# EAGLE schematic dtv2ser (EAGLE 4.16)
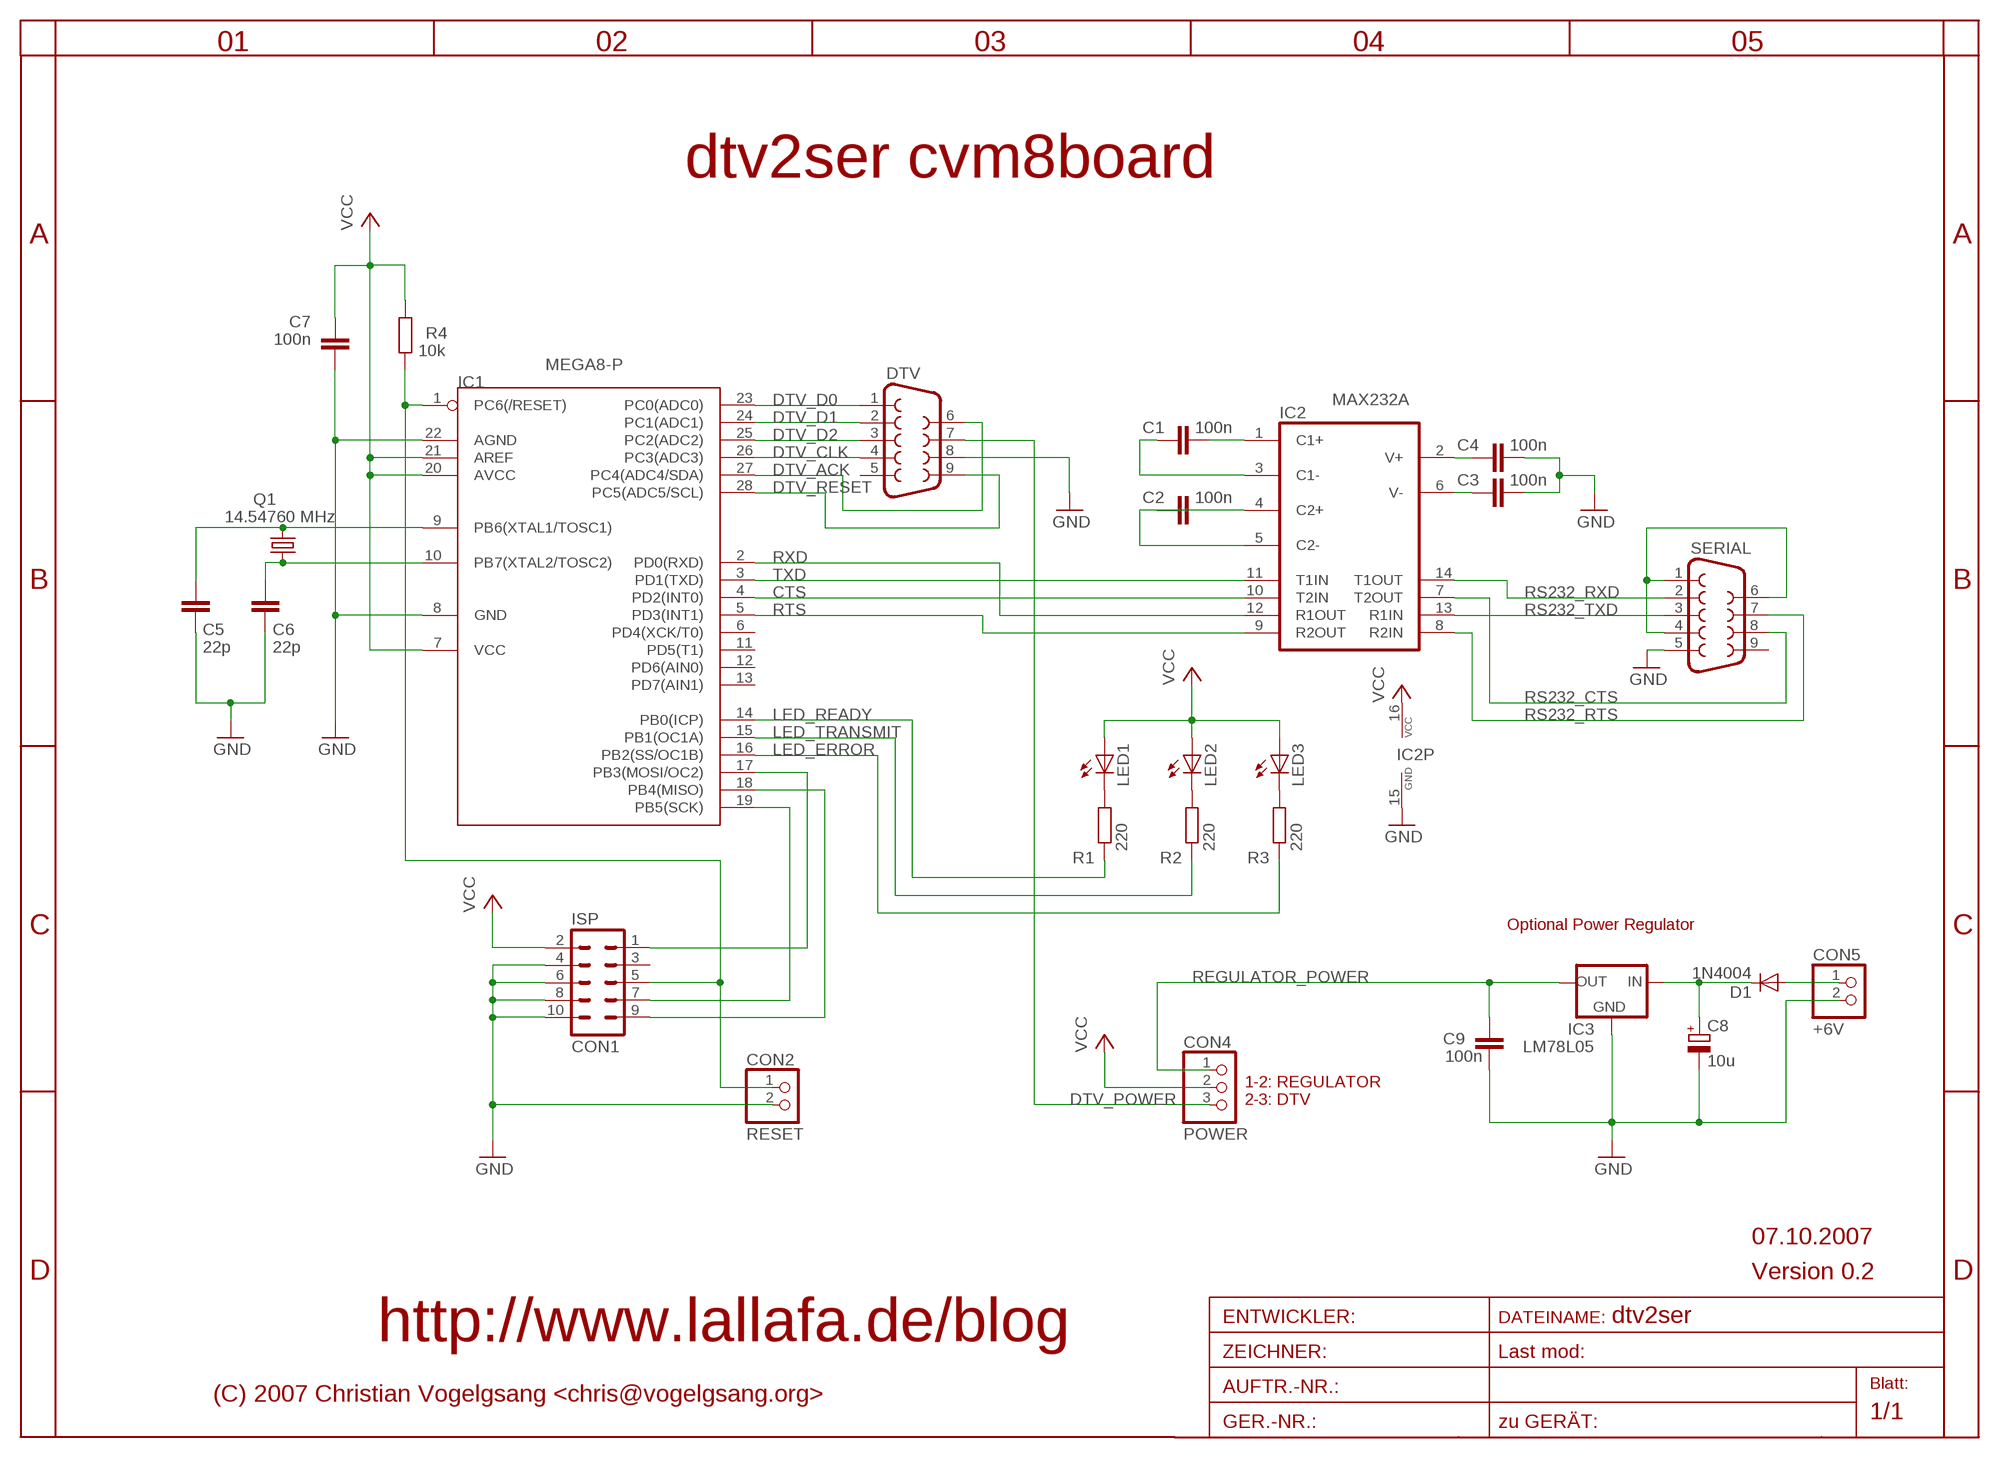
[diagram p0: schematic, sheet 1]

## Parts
C1  100n  C-EU025-025X050  [C025-025X050]
C2  100n  C-EU025-025X050  [C025-025X050]
C3  100n  C-EU025-025X050  [C025-025X050]
C4  100n  C-EU025-025X050  [C025-025X050]
C5  22p  C-EU025-025X050  [C025-025X050]
C6  22p  C-EU025-025X050  [C025-025X050]
C7  100n  C-EU025-025X050  [C025-025X050]
C8  10u  CPOL-EUE5-4  [E5-4]
C9  100n  C-EU025-025X050  [C025-025X050]
CON1  ISP  MA05-2  [MA05-2]
CON2  RESET  PINHD-1X2  [1X02]
CON4  POWER  PINHD-1X3  [1X03]
CON5  +6V  PINHD-1X2  [1X02]
D1  1N4004  [DO41-10]
DTV  F09HP  [F09HP]
IC1  MEGA8-P  [DIL28-3]
IC2  MAX232A  MAX232  [DIL16]
IC3  LM78L05  78LXX  [78LXX]
LED1  LED3MM  [LED3MM]
LED2  LED3MM  [LED3MM]
LED3  LED3MM  [LED3MM]
Q1  14.54760 MHz  CRYSTALHC49S  [HC49/S]
R1  220  R-EU_0204/7  [0204/7]
R2  220  R-EU_0204/7  [0204/7]
R3  220  R-EU_0204/7  [0204/7]
R4  10k  R-EU_R0402  [R0402]
SERIAL  F09HP  [F09HP]

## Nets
CON1: CON1.9 IC1.18(PB4(MISO))
CTS: IC1.4(PD2(INT0)) IC2.10(T2IN)
DTV_ACK: DTV.6 IC1.27(PC4(ADC4/SDA))
DTV_CLK: DTV.4 IC1.26(PC3(ADC3))
DTV_D0: DTV.1 IC1.23(PC0(ADC0))
DTV_D1: DTV.2 IC1.24(PC1(ADC1))
DTV_D2: DTV.3 IC1.25(PC2(ADC2))
DTV_POWER: CON4.3 DTV.7
DTV_RESET: DTV.9 IC1.28(PC5(ADC5/SCL))
GND: C3.1 C4.1 C5.1 C6.1 C7.2 C8.- C9.2 CON1.4 CON1.6 CON1.8 CON1.10 CON2.2 CON5.2 DTV.8 IC1.8(GND) IC1.22(AGND) IC2.15(GND) IC3.GND SERIAL.5
LED_ERROR: IC1.16(PB2(SS/OC1B)) R3.1
LED_READY: IC1.14(PB0(ICP)) R1.1
LED_TRANSMIT: IC1.15(PB1(OC1A)) R2.1
MAX232A: C1.2 IC2.3(C1-)
N$1: CON5.1 D1.A
N$2: C8.+ D1.C IC3.IN
N$4: C6.2 IC1.10(PB7(XTAL2/TOSC2)) Q1.1
N$5: CON1.5 CON2.1 IC1.1(PC6(/RESET)) R4.1
N$6: C5.2 IC1.9(PB6(XTAL1/TOSC1)) Q1.2
N$7: CON1.1 IC1.17(PB3(MOSI/OC2))
N$8: CON1.7 IC1.19(PB5(SCK))
N$17: C1.1 IC2.1(C1+)
N$19: C2.1 IC2.5(C2-)
N$20: C2.2 IC2.4(C2+)
N$21: C3.2 IC2.6(V-)
N$22: C4.2 IC2.2(V+)
N$28: SERIAL.1 SERIAL.4 SERIAL.6
N$29: LED1.K(C) R1.2
N$30: LED2.K(C) R2.2
N$31: LED3.K(C) R3.2
REGULATOR_POWER: C9.1 CON4.1 IC3.OUT
RS232_CTS: IC2.7(T2OUT) SERIAL.8
RS232_RTS: IC2.8(R2IN) SERIAL.7
RS232_RXD: IC2.14(T1OUT) SERIAL.2
RS232_TXD: IC2.13(R1IN) SERIAL.3
RTS: IC1.5(PD3(INT1)) IC2.9(R2OUT)
RXD: IC1.2(PD0(RXD)) IC2.12(R1OUT)
TXD: IC1.3(PD1(TXD)) IC2.11(T1IN)
VCC: C7.1 CON1.2 CON4.2 IC1.7(VCC) IC1.20(AVCC) IC1.21(AREF) IC2.16(VCC) LED1.A LED2.A LED3.A R4.2
Unconnected: CON1.3 DTV.5 IC1.6(PD4(XCK/T0)) IC1.11(PD5(T1)) IC1.12(PD6(AIN0)) IC1.13(PD7(AIN1)) SERIAL.9

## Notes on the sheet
- dtv2ser cvm8board
- Optional Power Regulator
- 1-2: REGULATOR
- 2-3: DTV
- 07.10.2007
- Version 0.2
- http://www.lallafa.de/blog
- (C) 2007 Christian Vogelgsang <chris@vogelgsang.org>

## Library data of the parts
C1-C7 C9 = rcl:C-EU: CAPACITOR, European symbol
C8 = rcl:CPOL-EU: POLARIZED CAPACITOR, European symbol
CON1 = con-lstb:MA05-2: PIN HEADER
CON2 CON5 = pinhead:PINHD-1X2: PIN HEADER
CON4 = pinhead:PINHD-1X3: PIN HEADER
D1 = diode:1N4004: DIODE
DTV SERIAL = con-subd:F09: SUB-D
IC1 = atmel:MEGA8-P: MICROCONTROLLER 8 Kbytes FLASH 1 kbytes SRAM 512 bytes EEPROM USART 4-channel 10 bit ADC 2-channel 8 bit ADC Source: avr.lbr
IC2 = maxim:MAX232: RS232 TRANSEIVER
IC3 = v-reg:78LXX: VOLTAGE REGULATOR
LED1-LED3 = led:LED: LED
Q1 = crystal:CRYSTAL: CRYSTAL
R1-R4 = rcl:R-EU_: RESISTOR, European symbol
